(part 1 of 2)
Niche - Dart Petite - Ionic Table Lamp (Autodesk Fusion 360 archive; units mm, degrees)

design "Marble Base - Ionic Table Lamp - 120V" references "Arca Tall", "Orb 8.5In - Solitaire Petite", "T9-5In", "T8 LED 11", "T9 - Bulb", "Facet Petite", "Marble Base - Silicone Gasket", "2-Pole Plug End", "Balon v2", "Dart", "Rubber Grommet", "Neoprene Pad", "Chinois", "Dart Petite", "Marble Base - Plastic Insert", "Trove - TL"
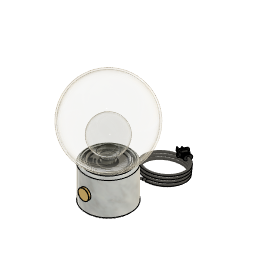
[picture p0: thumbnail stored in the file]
sketch "Sketch1" plane through (0, 0, 0) normal (0, 0, 1) x axis (1, 0, 0)
  circle C1 centre (0, 0) radius 63.5
  point P1 (0, 0)
  point P2 (0, 0)
  coincident P1 P2
extrude "Extrude1" new body sketch "Sketch1" along normal blind 101.6 bodies "Marble Base"
sketch "Sketch2" plane through (0, 0, 101.6) normal (0, 0, 1) x axis (-1, 0, 0)
  circle C1 centre (0, 0) radius 63.5
  circle C2 centre (0, 0) radius 53.975
  concentric C1 C2
  dimension "d3" diameter C2 = 107.95
extrude "Extrude2" cut sketch "Sketch2" profile of C2 against normal blind 34.925
sketch "Sketch3" plane through (0, 0, 66.675) normal (0, 0, 1) x axis (-1, 0, 0)
  circle C1 centre (0, 0) radius 53.975
  circle C2 centre (0, 0) radius 49.276
  point P1 (0, 0)
  point P3 (0, 0)
  coincident P1 P3
  dimension "d6" diameter C2 = 98.552
extrude "Extrude3" cut sketch "Sketch3" profile of C2 against normal blind 45.72
sketch "Sketch4" plane through (0, 0, 0) normal (0, 1, 0) x axis (1, 0, 0)
  circle C1 centre (0, -50.8) radius 3.81
  dimension "d9" diameter C1 = 7.62
extrude "Extrude4" cut sketch "Sketch4" against normal blind 127
sketch "Sketch5" plane through (0, 0, 0) normal (0, 1, 0) x axis (1, 0, 0)
  line L1 (0, -25.4) -> (0, 0)
  line L2 (0, -30.48) -> (0, -25.4)
  circle C1 centre (0, -30.48) radius 5.08
  point P1 (0, 0)
  point P2 (0, 0)
  point P4 (0, -30.48)
  point P5 (0, -30.48)
  coincident P1 P2
  vertical L1
  parallel L1 L2
  coincident P4 P5
  dimension "d12" diameter C1 = 10.16
extrude "Extrude5" cut sketch "Sketch5" profile of C1 along normal blind 114.3
fillet "Fillet1" radius 6.35 3.175 4.064
derived_base_feature "Derived Base Feature1" bodies "Rotary Switch"
derived_base_feature "Derived Base Feature1" bodies "Coiled - SVT (Blk Fabric)"
derived_base_feature "Derived Base Feature1" bodies "Glass Globe"
derived_base_feature "Derived Base Feature1" bodies "Metal Housing"
derived_base_feature "Derived Base Feature1" bodies "Metal Socket Cover"
derived_base_feature "Derived Base Feature1" bodies "Porcelain Socket"
derived_base_feature "Derived Base Feature1" bodies "Brass Dial - Dimmer Knob"
component_from_bodies "Body->Comp1"
offset_faces "OffsetFaces1" distance 12.7
offset_faces "OffsetFaces2" distance -12.7
derived_base_feature "Derived Base Feature1" bodies "Solitaire Petite"
move "Move1"
offset_faces "OffsetFaces1" distance 20.32
move "Move2"
extrude "Extrude6" add of existing geometry blind 25.4
offset_faces "OffsetFaces2" distance -3.81
fillet "Fillet2" radius 2.54
move "Move3"
derived_base_feature "Derived Base Feature2" bodies "Facet Petite"
move "Move4"
offset_faces "OffsetFaces1" distance 2.54
move "Move1"
derived_base_feature "Derived Base Feature1" bodies "Body1"
derived_base_feature "Derived Base Feature1" bodies "Body1"
derived_base_feature "Derived Base Feature1" bodies "Body1"
derived_base_feature "Derived Base Feature1" bodies "Body1"
derived_base_feature "Derived Base Feature1" bodies "Body1"
derived_base_feature "Derived Base Feature1" bodies "Body1", "Body2"
derived_base_feature "Derived Base Feature1" bodies "Body1"
position "Position1"
external_derived "ExternalDerived5" bodies "Plastic Insert"
derived_instance "DerivedInstance15"
offset_faces "OffsetFaces1" distance 3.81
offset_faces "OffsetFaces2" distance -1.0414
move "Move6"
external_derived "ExternalDerived6" sketch "Sketch3" bodies "Silicone Gasket"
derived_instance "DerivedInstance16"
offset_faces "OffsetFaces3" distance -10.795
move "Move1"
move_face "MoveFace1"
position "Position2"
position "Position3"
position "Position4"
position "Position5"
move "Move2"
position "Position6"
offset_faces "OffsetFaces2" distance -7.62
chamfer "Chamfer1" distance 0.381
remove_instance "RemoveInstance1"
remove_instance "RemoveInstance2"
remove_instance "RemoveInstance3"
remove_instance "RemoveInstance4"
move "Move1"
derived_base_feature "Derived Base Feature5" bodies "Oculo Petite"
align "Align1"
external_derived "ExternalDerived8"
derived_base_feature "Derived Base Feature7" bodies "Balon v2"
derived_base_feature "Derived Base Feature8" bodies "Balon v3"
align "Align3"
align "Align4"
external_derived "ExternalDerived10"
component_insert "Component Insert1"
position "Position7"
position "Position8"
derived_base_feature "Derived Base Feature11" bodies "Trove - TL"
move "Move10"
move "Move11"
remove_instance "RemoveInstance5"
split "Split1" bodies "Trove - TL (1)"
remove_body "RemoveBody2"
remove_body "RemoveBody3"
external_derived "ExternalDerived13" bodies "Trove - TL"
derived_instance "DerivedInstance20"
remove_body "RemoveBody4"
remove_body "RemoveBody5"
component_insert "Component Insert2"
component_insert "Component Insert3"
component_from_bodies "Body->Comp2"
remove_body "RemoveBody7"
move "Move12"
move "Move13"
sketch "Sketch6" plane through (0, 0, 97.917) normal (0, 0, 1) x axis (-1, 0, 0)
  circle C1 centre (0, 0) radius 41.275
  circle C2 centre (0, 0) radius 19.685
  arc A1 centre (0, 0) radius 29.3982 clockwise from (-27.6283, 10.0466) to (27.6283, 10.0466)
  arc A2 centre (0, 0) radius 26.2232 clockwise from (-24.6444, 8.9616) to (24.6444, 8.9616)
  arc A3 centre (0, 0) radius 32.5732 clockwise from (-30.6121, 11.1317) to (30.6121, 11.1317)
  arc A4 centre (0, 0) radius 35.7482 clockwise from (-33.596, 12.2167) to (33.596, 12.2167)
  point P1 (0, 0)
  point P3 (0, 0)
  coincident P1 P3
  dimension "d37" = -3.175
  dimension "d38" = 3.175
  dimension "d39" = 6.35
  dimension "d40" Text1-Height = 2.54
  dimension "d41" Text2-Height = 2.54
  dimension "d42" Text3-Height = 2.54
  dimension "d43" Text4-Height = 2.54
extrude "Extrude1" cut sketch "Sketch6" against normal blind 0.254
external_derived "ExternalDerived14" bodies "Rubber Grommet"
derived_instance "DerivedInstance19"
external_derived "ExternalDerived15" bodies "2-Pole Plug End"
derived_instance "DerivedInstance18"
external_derived "ExternalDerived16" bodies "Neoprene Pad"
derived_instance "DerivedInstance17"
position "Position9"
position "Position10"
position "Position11"
position "Position12"
external_derived "ExternalDerived17" bodies "Chinois"
derived_instance "DerivedInstance21"
position "Position13"
move "Move3"
remove_body "RemoveBody8"
component_insert "Component Insert4"
offset_faces "OffsetFaces3" distance 50.8
component_insert "Component Insert5"
position "Position14"
external_derived "ExternalDerived18" bodies "Dart Grand"
derived_instance "DerivedInstance22"
offset_faces "OffsetFaces1" distance -10.16
position "Position15"
external_derived "ExternalDerived19" bodies "Dart Petite"
derived_instance "DerivedInstance23"
offset_faces "OffsetFaces1" distance -10.16
position "Position16"
component_insert "Component Insert6"
position "Position17"
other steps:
derived_base_feature "Derived Base Feature1" bodies "Trove - TL"
derived_base_feature "Derived Base Feature1" bodies "Chinois"
derived_base_feature "Derived Base Feature1" bodies "Dart Grand"
derived_base_feature "Derived Base Feature1" bodies "Dart Petite"
derived_base_feature "Derived Base Feature1" bodies "Rubber Grommet"
derived_base_feature "Derived Base Feature1" bodies "Neoprene Pad"
derived_base_feature "Derived Base Feature1" bodies "2-Pole Plug End"
move "Move1"
derived_base_feature "Derived Base Feature1" bodies "Plastic Insert"
derived_base_feature "Derived Base Feature1" bodies "Silicone Gasket"
base_feature "Base Feature1" bodies "Oculo Petite", "Arca Petite"
base_feature "Base Feature1" bodies "Marble Base"
move "Move8"
derived_base_feature "Derived Base Feature"
create_component "CreateComponent1"
create_component "CreateComponent2"
create_component "CreateComponent3"
create_component "CreateComponent4"
create_component "CreateComponent5"
create_component "CreateComponent6"
create_component "CreateComponent7"
create_component "CreateComponent8"
remove_body "RemoveBody1"
create_component "CreateComponent9"
create_component "CreateComponent10"
create_component "CreateComponent11"
create_component "CreateComponent12"
create_component "CreateComponent13"
create_component "CreateComponent14"
create_component "CreateComponent15"
create_component "CreateComponent16"
create_component "CreateComponent17"
create_component "CreateComponent18"
remove_body "RemoveBody6"
create_component "CreateComponent19"
create_component "CreateComponent20"
create_component "CreateComponent21"
create_component "CreateComponent22"
create_component "CreateComponent23"
create_component "CreateComponent24"
create_component "CreateComponent25"
named bodies: "Marble Base", "Rotary Switch", "Coiled - SVT (Blk Fabric)", "Glass Globe", "Metal Housing", "Metal Socket Cover", "Porcelain Socket", "Brass Dial - Dimmer Knob", "Solitaire Petite", "Facet Petite", "Body1", "Body2", "Plastic Insert", "Silicone Gasket", "Oculo Petite", "Balon v2", "Balon v3", "Trove - TL", "Trove - TL (1)", "Arca Petite", "Neoprene Pad", "2-Pole Plug End", "Rubber Grommet", "Chinois", "Dart Grand", "Dart Petite"

design "Dart Petite"
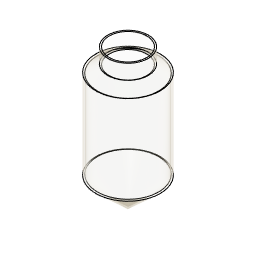
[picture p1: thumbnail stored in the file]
sketch "Sketch1" plane through (0, 0, 0) normal (0, 0, 1) x axis (1, 0, 0)
work_plane "WorkPlane1" AlongDistance 76.2
sketch "Sketch2" plane through (0, 0, 76.2) normal (0, 0, 1) x axis (1, 0, 0)
sketch "Sketch3" plane through (0, 0, 76.2) normal (0, 0, 1) x axis (1, 0, 0)
sketch "Sketch4" plane through (0, 0, 76.2) normal (0, 0, 1) x axis (1, 0, 0)
  circle C1 centre (0, 0) radius 82.55
  point P1 (0, 0)
  point P2 (0, 0)
  coincident P1 P2
  dimension "d2" diameter C1 = 165.1
loft "Loft1" sketch "Sketch4" bodies "Dart Petite"
extrude "Extrude1" add of existing geometry blind 228.6
work_plane "WorkPlane2" AlongDistance 19.05
sketch "Sketch5" plane through (0, 0, 323.85) normal (0, 0, 1) x axis (1, 0, 0)
  circle C1 centre (0, 0) radius 52.07
  point P1 (0, 0)
  point P2 (0, 0)
  coincident P1 P2
  dimension "d6" diameter C1 = 104.14
loft "Loft2" sketch "Sketch5"
extrude "Extrude2" add of existing geometry blind 38.1
shell "Shell3" innerThickness 3.81
component_from_bodies "Body->Comp"
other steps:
base_feature "Base Feature" bodies "Dart Petite"
create_component "CreateComponent1"
remove_body "RemoveBody1"
named bodies: "Dart Petite"

design "Neoprene Pad"
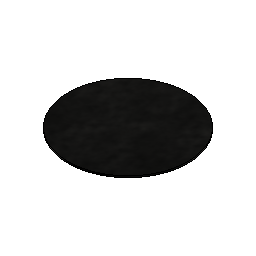
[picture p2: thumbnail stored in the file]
sketch "Sketch1" plane through (0, 0, 0) normal (0, 0, 1) x axis (1, 0, 0)
  circle C1 centre (0, 0) radius 57.15
  point P1 (0, 0)
  point P2 (0, 0)
  coincident P1 P2
extrude "Extrude1" new body sketch "Sketch1" along normal blind 1.5875 bodies "Neoprene Pad"
component_from_bodies "Body->Comp"
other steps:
base_feature "Base Feature" bodies "Neoprene Pad"
create_component "CreateComponent1"
remove_body "RemoveBody1"
named bodies: "Neoprene Pad"

design "T9 - Bulb"
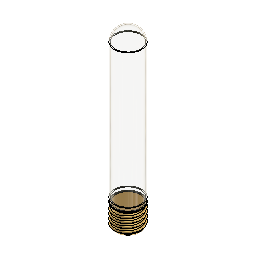
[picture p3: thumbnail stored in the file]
sketch "Sketch1" plane through (0, 0, 0) normal (0, 1, 0) x axis (1, 0, 0)
  line L1 (0, -166.37) -> (0, 0)
  line L2 (13.97, -13.97) -> (13.97, -152.4)
  line L3 (-13.97, -152.4) -> (-13.97, -13.97)
  line L4 (0, 0) -> (0, -166.37)
  line L5 (12.97, -13.97) -> (12.97, -152.4)
  line L6 (-12.97, -152.4) -> (-12.97, -13.97)
  line L7 (-12.3978, -10.16) -> (-13.4404, -10.16)
  line L8 (13.4404, -10.16) -> (12.3978, -10.16)
  arc A1 centre (0, -152.4) radius 13.97 clockwise from (13.97, -152.4) to (-13.97, -152.4)
  arc A2 centre (0, -152.4) radius 12.97 clockwise from (12.97, -152.4) to (-12.97, -152.4)
  arc A3 centre (0, -13.97) radius 13.97 clockwise from (13.4404, -10.16) to (13.97, -13.97)
  arc A4 centre (0, -13.97) radius 13.97 clockwise from (-13.97, -13.97) to (-13.4404, -10.16)
  arc A5 centre (0, -13.97) radius 12.97 clockwise from (12.3978, -10.16) to (12.97, -13.97)
  arc A6 centre (0, -13.97) radius 12.97 clockwise from (-12.97, -13.97) to (-12.3978, -10.16)
  point P1 (0, 0)
  point P2 (0, 0)
  point P3 (0, -166.37)
  point P10 (0, 0)
  point P17 (13.4404, -10.16)
  point P19 (12.3978, -10.16)
  point P4 (13.97, -152.4)
  point P5 (13.97, -13.97)
  coincident P1 P2
  vertical L1
  tangent L2 A3
  tangent L3 A3
  parallel L2 L3
  tangent L3 A1
  tangent L2 A1
  midpoint P3 A1
  coincident P1 P10
  perpendicular L1 L7
  coincident P17 L7
  concentric A3 A4
  coincident P10 A3
  concentric A1 A2
  tangent L5 A2
  tangent L5 A5
  tangent L6 A5
  tangent L6 A2
  coincident P19 L7
  concentric A5 A6
  collinear L7 L8
  dimension "d6" distance L2 L3 = 27.94
  dimension "d7" distance P4 P5 = 138.43
revolve "Revolve1" sketch "Sketch1" AlongAngle 360 bodies "T9"
derived_base_feature "Derived Base Feature" bodies "E26 Base"
align "Align1"
move "Move1"
component_from_bodies "Body->Comp1"
component_from_bodies "Body->Comp2"
copy_paste "CutPaste1"
copy_paste "CutPaste2"
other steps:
base_feature "Base Feature1" bodies "T9"
base_feature "Base Feature1" bodies "E26 Base"
create_component "CreateComponent1"
create_component "CreateComponent2"
remove_body "RemoveBody1"
create_component "CreateComponent3"
remove_body "RemoveBody2"
remove_instance "RemoveInstance1"
remove_instance "RemoveInstance2"
named bodies: "T9", "E26 Base"

design "Facet Petite"
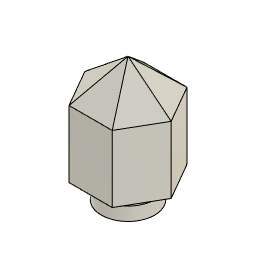
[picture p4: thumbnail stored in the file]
sketch "Sketch7" plane through (0, 0, 0) normal (1, 0, 0) x axis (0, 1, 0)
sketch "Sketch8" plane through (0, 0, 0) normal (0, 0, 1) x axis (1, 0, 0)
  circle C1 centre (0, 0) radius 50.8
  point P1 (0, 0)
  point P2 (0, 0)
  coincident P1 P2
  dimension "d17" diameter C1 = 101.6
extrude "Extrude5" new body sketch "Sketch8" along normal blind 25.4 and against normal blind 25.4
work_plane "WorkPlane1" AlongDistance 17.78
sketch "Sketch10" plane through (0, 0, 25.4) normal (0, 0, 1) x axis (-1, 0, 0)
  circle C1 centre (0, 0) radius 50.8
sketch "Sketch12" plane through (0, 0, 43.18) normal (0, 0, 1) x axis (1, 0, 0)
  line L1 (-82.1223, 0) -> (-41.0612, 71.12)
  line L2 (-41.0612, -71.12) -> (-82.1223, 0)
  line L3 (41.0612, -71.12) -> (-41.0612, -71.12)
  line L4 (82.1223, 0) -> (41.0612, -71.12)
  line L5 (41.0612, 71.12) -> (82.1223, 0)
  line L6 (-41.0612, 71.12) -> (41.0612, 71.12)
  point P1 (0, 0)
  point P8 (0, 0)
  coincident P1 P8
  dimension "d22" distance P8 L6 = 71.12
sketch "Sketch15" plane through (0, 0, 0) normal (0, 1, 0) x axis (1, 0, 0)
  line L1 (53.7365, -21.6801) -> (82.1223, -43.18)
  line L2 (-50.8, -25.4) -> (-82.1223, -43.18)
  point P2 (82.1223, -43.18)
  point P3 (82.1223, -43.18)
  point P5 (-82.1223, -43.18)
  point P7 (-82.1223, -43.18)
  point P6 (-50.8, -25.4)
  point P8 (-50.8, -25.4)
  coincident P2 P3
  coincident P5 P7
  coincident P6 P8
sketch "Sketch17" plane through (0, 0, 25.4) normal (0, 0, 1) x axis (-1, 0, 0)
  line L1 (51.3255, 0) -> (0, 0)
  line L2 (73.3235, 0) -> (0, 0)
  line L3 (-41.0612, -71.12) -> (-25.4, -43.9941)
  line L4 (-36.6617, -63.5) -> (-25.4, -43.9941)
  line L5 (78.4305, 0) -> (0, 0)
  line L6 (41.0612, -71.12) -> (25.4, -43.9941)
  line L7 (25.4, 43.9941) -> (41.0612, 71.12)
  line L8 (73.3235, 0) -> (0, 0)
  line L9 (-25.4, 43.9941) -> (-41.0612, 71.12)
  line L10 (0, 0) -> (0, 0)
  circle C1 centre (0, 0) radius 50.8
  point P1 (0, 0)
  point P4 (0, 0)
  point P2 (-41.0612, -71.12)
  point P6 (-41.0612, -71.12)
  point P3 (0, 0)
  point P7 (0, 0)
  point P9 (-25.4, -43.9941)
  point P12 (41.0612, -71.12)
  point P13 (41.0612, -71.12)
  point P15 (25.4, -43.9941)
  point P16 (41.0612, 71.12)
  point P17 (41.0612, 71.12)
  point P18 (25.4, 43.9941)
  point P19 (-41.0612, 71.12)
  point P20 (-41.0612, 71.12)
  point P21 (0, 0)
  point P23 (-25.4, 43.9941)
  point P25 (0, 0)
  point P24 (0, 0)
  point P26 (0, 0)
  horizontal L1
  coincident P1 P4
  coincident P2 P6
  horizontal L2
  coincident P3 P7
  coincident C1 P9
  coincident P12 P13
  horizontal L5
  coincident C1 P15
  coincident P16 P17
  coincident C1 P18
  coincident P19 P20
  horizontal L8
  coincident P1 P21
  coincident C1 P23
  coincident P1 P25
  coincident P24 P26
extrude "Extrude6" new body sketch "Sketch12" along normal blind 127
work_plane "WorkPlane2" AlongDistance 66.04
sketch "Sketch18" plane through (0, 0, 236.22) normal (0, 0, 1) x axis (1, 0, 0)
  line L1 (41.0612, -71.12) -> (0, 0)
  line L2 (82.1223, 0) -> (0, 0)
  line L3 (41.0612, 71.12) -> (0, 0)
  line L4 (-41.0612, 71.12) -> (0, 0)
  line L5 (-82.1223, 0) -> (0, 0)
  line L6 (-41.0612, -71.12) -> (0, 0)
  point P1 (0, 0)
  point P3 (0, 0)
  point P2 (41.0612, -71.12)
  point P4 (41.0612, -71.12)
  point P6 (0, 0)
  point P5 (82.1223, 0)
  point P7 (82.1223, 0)
  point P9 (0, 0)
  point P8 (41.0612, 71.12)
  point P10 (41.0612, 71.12)
  point P12 (0, 0)
  point P11 (-41.0612, 71.12)
  point P13 (-41.0612, 71.12)
  point P15 (0, 0)
  point P14 (-82.1223, 0)
  point P16 (-82.1223, 0)
  point P18 (0, 0)
  point P17 (-41.0612, -71.12)
  point P19 (-41.0612, -71.12)
  coincident P1 P3
  coincident P2 P4
  coincident P1 P6
  coincident P5 P7
  coincident P1 P9
  coincident P8 P10
  coincident P1 P12
  coincident P11 P13
  coincident P1 P15
  coincident P14 P16
  coincident P1 P18
  coincident P17 P19
loft "Loft1"
loft "Loft2" sketch "Sketch17"
component_from_bodies "Body->Comp"
extrude "Extrude1" cut of existing geometry blind -25.4
shell "Shell2" innerThickness 3.81
fillet "Fillet1" radius 7.62
fillet "Fillet2" radius 6.35
fillet "Fillet3" radius 6.35
fillet "Fillet4" radius 6.35
fillet "Fillet5" radius 6.35
fillet "Fillet6" radius 6.35
fillet "Fillet7" radius 3.81
fillet "Fillet8" radius 6.35
fillet "Fillet9" radius 6.35
fillet "Fillet10" radius 6.35
fillet "Fillet11" radius 6.35
fillet "Fillet12" radius 6.35
fillet "Fillet13" radius 2.286
shell "Shell1" innerThickness 2.54
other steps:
base_feature "Base Feature"
create_component "CreateComponent3"
remove_body "RemoveBody2"

design "Marble Base - Silicone Gasket"
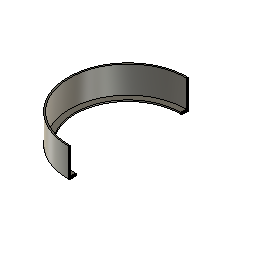
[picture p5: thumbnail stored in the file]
sketch "Sketch1" plane through (0, 0, 0) normal (0, 0, 1) x axis (1, 0, 0)
  circle C1 centre (0, 0) radius 53.34
  point P1 (0, 0)
  point P2 (0, 0)
  coincident P1 P2
extrude "Extrude1" new body sketch "Sketch1" along normal blind 25.4 bodies "Silicone Gasket"
shell "Shell1" innerThickness 1.27
sketch "Sketch2" plane through (0, 0, 1.27) normal (0, 0, 1) x axis (-1, 0, 0)
  circle C1 centre (0, 0) radius 52.07
  circle C2 centre (0, 0) radius 46.99
  concentric C1 C2
extrude "Extrude2" cut sketch "Sketch2" profile of C2 against normal blind 12.7
component_from_bodies "Body->Comp"
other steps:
base_feature "Base Feature" bodies "Silicone Gasket"
create_component "CreateComponent1"
remove_body "RemoveBody1"
named bodies: "Silicone Gasket"

design "Balon v2"
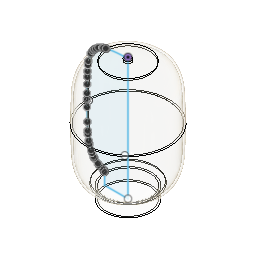
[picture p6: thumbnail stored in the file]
derived_base_feature "Derived Base Feature" bodies "Balon"
work_plane "WorkPlane1" AlongDistance 0
sketch "Sketch1" plane through (0, 0, 0) normal (0, 1, 0) x axis (1, 0, 0)
  line L1 (0, 317.5) -> (0, 2.9083)
  curve K1 (-82.9821, 124.2212) -> (-50.8, 237.8015)
  curve K2 (-51.0925, 237.681) -> (-50.8, 237.8015)
  curve K3 (-51.3855, 237.5558) -> (-51.0925, 237.681)
  curve K4 (-54.7608, 236.0513) -> (-51.3855, 237.5558)
  curve K5 (-57.9615, 234.05) -> (-54.7608, 236.0513)
  curve K6 (-67.2727, 226.749) -> (-57.9615, 234.05)
  curve K7 (-69.0552, 224.2615) -> (-67.2727, 226.749)
  curve K8 (-72.1872, 218.7832) -> (-69.0552, 224.2615)
  curve K9 (-74.1213, 215.1556) -> (-72.1872, 218.7832)
  curve K10 (-78.3031, 204.3965) -> (-74.1213, 215.1556)
  curve K11 (-79.7275, 197.3397) -> (-78.3031, 204.3965)
  curve K12 (-81.3333, 185.4664) -> (-79.7275, 197.3397)
  curve K13 (-81.6254, 178.4008) -> (-81.3333, 185.4664)
  curve K14 (-82.49, 152.2133) -> (-81.6254, 178.4008)
  curve K15 (-82.9821, 136.067) -> (-82.49, 152.2133)
  curve K16 (-82.9821, 124.2212) -> (-82.9821, 136.067)
  curve K17 (50.8, 237.7999) -> (82.9821, 124.2212)
  curve K18 (82.9821, 140.3031) -> (82.9821, 124.2212)
  curve K19 (81.9353, 169.4257) -> (82.9821, 140.3031)
  curve K20 (81.3621, 183.6489) -> (81.9353, 169.4257)
  curve K21 (80.9478, 189.8724) -> (81.3621, 183.6489)
  curve K22 (77.8147, 206.9858) -> (80.9478, 189.8724)
  curve K23 (74.9652, 213.2153) -> (77.8147, 206.9858)
  curve K24 (69.4688, 224.1531) -> (74.9652, 213.2153)
  curve K25 (67.2512, 226.458) -> (69.4688, 224.1531)
  curve K26 (61.5696, 231.3138) -> (67.2512, 226.458)
  curve K27 (57.377, 234.6711) -> (61.5696, 231.3138)
  curve K28 (52.0556, 237.2628) -> (57.377, 234.6711)
  curve K29 (51.4313, 237.5413) -> (52.0556, 237.2628)
  curve K30 (50.8, 237.7999) -> (51.4313, 237.5413)
  line L2 (-50.8, 317.5) -> (-50.8, 237.8015)
  line L3 (50.8, 317.5) -> (50.8, 237.7999)
  line L4 (-19.0713, 6.7501) -> (-19.0713, 6.7501)
  curve K31 (82.9821, 124.1958) -> (40.1509, 7.3012)
  curve K32 (41.8198, 7.6176) -> (40.1509, 7.3012)
  curve K33 (43.2113, 8.0663) -> (41.8198, 7.6176)
  curve K34 (47.0139, 9.2854) -> (43.2113, 8.0663)
  curve K35 (47.3314, 9.3805) -> (47.0139, 9.2854)
  curve K36 (50.1192, 10.3272) -> (47.3314, 9.3805)
  curve K37 (51.833, 11.0085) -> (50.1192, 10.3272)
  curve K38 (57.8313, 14.1895) -> (51.833, 11.0085)
  curve K39 (61.4491, 17.0488) -> (57.8313, 14.1895)
  curve K40 (66.8203, 21.5867) -> (61.4491, 17.0488)
  curve K41 (68.5372, 23.5528) -> (66.8203, 21.5867)
  curve K42 (71.2201, 27.8971) -> (68.5372, 23.5528)
  curve K43 (74.7424, 33.8984) -> (71.2201, 27.8971)
  curve K44 (78.2342, 44.8406) -> (74.7424, 33.8984)
  curve K45 (79.6792, 50.3463) -> (78.2342, 44.8406)
  curve K46 (81.3558, 63.5576) -> (79.6792, 50.3463)
  curve K47 (81.6386, 70.4415) -> (81.3558, 63.5576)
  curve K48 (82.4897, 96.2198) -> (81.6386, 70.4415)
  curve K49 (82.9814, 112.3523) -> (82.4897, 96.2198)
  curve K50 (82.9821, 124.1958) -> (82.9814, 112.3523)
  curve K51 (-40.1501, 7.301) -> (-82.9821, 124.1958)
  curve K52 (-82.9813, 110.5256) -> (-82.9821, 124.1958)
  curve K53 (-82.2545, 88.8594) -> (-82.9813, 110.5256)
  curve K54 (-81.6277, 70.519) -> (-82.2545, 88.8594)
  curve K55 (-81.3572, 64.3441) -> (-81.6277, 70.519)
  curve K56 (-79.4149, 46.8924) -> (-81.3572, 64.3441)
  curve K57 (-76.5204, 38.9768) -> (-79.4149, 46.8924)
  curve K58 (-73.5142, 32.2947) -> (-76.5204, 38.9768)
  curve K59 (-72.5556, 30.3818) -> (-73.5142, 32.2947)
  curve K60 (-69.7914, 25.3691) -> (-72.5556, 30.3818)
  curve K61 (-68.3824, 23.4028) -> (-69.7914, 25.3691)
  curve K62 (-64.5419, 19.5456) -> (-68.3824, 23.4028)
  curve K63 (-62.3002, 17.7646) -> (-64.5419, 19.5456)
  curve K64 (-53.6583, 11.1976) -> (-62.3002, 17.7646)
  curve K65 (-49.6968, 10.1396) -> (-53.6583, 11.1976)
  curve K66 (-43.4141, 8.1331) -> (-49.6968, 10.1396)
  curve K67 (-41.9704, 7.6516) -> (-43.4141, 8.1331)
  curve K68 (-40.1963, 7.3098) -> (-41.9704, 7.6516)
  curve K69 (-40.1732, 7.3054) -> (-40.1963, 7.3098)
  curve K70 (-40.1501, 7.301) -> (-40.1732, 7.3054)
  line L5 (-82.9821, 124.1958) -> (-82.9821, 124.2212)
  line L6 (82.9821, 124.2212) -> (82.9821, 124.1958)
  line L7 (0, 317.5) -> (-50.8, 317.5)
  line L8 (7.2015, 3.048) -> (0, 3.048)
  line L9 (0, 3.048) -> (-7.2015, 3.048)
  arc A1 centre (0, 188.595) radius 185.6867 clockwise from (-7.2015, 3.048) to (-40.1502, 7.301)
  arc A2 centre (0, 188.595) radius 185.6867 clockwise from (40.151, 7.3012) to (7.2015, 3.048)
  point P38 (-40.1502, 7.301)
  point P43 (40.1509, 7.3012)
  point P62 (-40.1501, 7.301)
  point P81 (40.151, 7.3012)
  point P84 (0, 3.048)
  vertical L1
  horizontal L4
  coincident P38 K51
  symmetric L1 A1 A2
  coincident A2 P43
  coincident A1 P62
  coincident K31 P81
  perpendicular L2 L7
  horizontal L8
  coincident L1 P84
  horizontal L9
revolve "Revolve1" sketch "Sketch1" AlongAngle 360
shell "Shell1" innerThickness 3.81
fillet "Fillet1" radius 6.35
offset_faces "OffsetFaces1" distance -50.8
move "Move1"
move "Move2"
component_from_bodies "Body->Comp1"
component_from_bodies "Body->Comp2"
sketch "Sketch2" plane through (0, 0, 0) normal (0, 1, 0) x axis (1, 0, 0)
  line L1 (-85.5221, 124.2212) -> (-85.5221, 124.1961)
  curve K1 (-58.9057, 236.4383) -> (-50.8, 241.7989)
  curve K2 (-50.8, 241.554) -> (-50.8, 241.7989)
  curve K3 (-50.904, 240.933) -> (-50.8, 241.554)
  curve K4 (-51.2936, 240.2837) -> (-50.904, 240.933)
  curve K5 (-51.734, 239.7561) -> (-51.2936, 240.2837)
  curve K6 (-53.328, 238.5038) -> (-51.734, 239.7561)
  curve K7 (-54.0892, 238.1997) -> (-53.328, 238.5038)
  curve K8 (-58.9057, 236.4383) -> (-54.0892, 238.1997)
  curve K9 (-89.3309, 124.2212) -> (-58.9057, 236.4383)
  curve K10 (-62.6336, 234.9735) -> (-58.9057, 236.4383)
  curve K11 (-65.581, 233.1032) -> (-62.6336, 234.9735)
  curve K12 (-73.0224, 227.0019) -> (-65.581, 233.1032)
  curve K13 (-74.8981, 224.836) -> (-73.0224, 227.0019)
  curve K14 (-78.1104, 219.6097) -> (-74.8981, 224.836)
  curve K15 (-80.2663, 215.561) -> (-78.1104, 219.6097)
  curve K16 (-84.0943, 205.8277) -> (-80.2663, 215.561)
  curve K17 (-85.4655, 200.1154) -> (-84.0943, 205.8277)
  curve K18 (-87.4092, 188.5789) -> (-85.4655, 200.1154)
  curve K19 (-87.7349, 182.3889) -> (-87.4092, 188.5789)
  curve K20 (-88.4233, 165.9645) -> (-87.7349, 182.3889)
  curve K21 (-89.328, 138.6964) -> (-88.4233, 165.9645)
  curve K22 (-89.3309, 124.2212) -> (-89.328, 138.6964)
  line L2 (-89.3309, 124.1958) -> (-89.3309, 124.2212)
  curve K23 (-46.5001, 7.301) -> (-89.3309, 124.1958)
  curve K24 (-89.3314, 112.4293) -> (-89.3309, 124.1958)
  curve K25 (-88.8181, 95.3068) -> (-89.3314, 112.4293)
  curve K26 (-88.346, 81.2892) -> (-88.8181, 95.3068)
  curve K27 (-88.0298, 70.4902) -> (-88.346, 81.2892)
  curve K28 (-87.1514, 58.328) -> (-88.0298, 70.4902)
  curve K29 (-86.3326, 50.6119) -> (-87.1514, 58.328)
  curve K30 (-81.0932, 33.6688) -> (-86.3326, 50.6119)
  curve K31 (-77.3163, 27.4309) -> (-81.0932, 33.6688)
  curve K32 (-74.8955, 23.6666) -> (-77.3163, 27.4309)
  curve K33 (-73.5108, 22.0741) -> (-74.8955, 23.6666)
  curve K34 (-70.2346, 19.0457) -> (-73.5108, 22.0741)
  curve K35 (-64.8094, 14.3548) -> (-70.2346, 19.0457)
  curve K36 (-56.6696, 10.3041) -> (-64.8094, 14.3548)
  curve K37 (-54.0053, 9.483) -> (-56.6696, 10.3041)
  curve K38 (-49.1487, 7.9411) -> (-54.0053, 9.483)
  curve K39 (-48.3482, 7.6526) -> (-49.1487, 7.9411)
  curve K40 (-46.5001, 7.301) -> (-48.3482, 7.6526)
  line L3 (0, 266.7) -> (0, 0)
  line L4 (0, 3.048) -> (-7.7894, 3.048)
  line L5 (-50.8, 266.7) -> (-50.8, 241.7989)
  line L6 (0, 266.7) -> (-50.8, 266.7)
  arc A1 centre (-6.9779, 188.7329) radius 185.6867 clockwise from (-7.7894, 3.048) to (-46.5001, 7.301)
  point P1 (0, 0)
  point P44 (0, 0)
  point P46 (0, 3.048)
  point P5 (-50.8, 241.554)
  point P49 (0, 266.7)
  coincident P1 P44
  coincident L3 P46
  coincident P5 L5
  coincident L3 P49
revolve "Revolve2" sketch "Sketch2" AlongAngle 360 bodies "Balon v3"
shell "Shell2" innerThickness 3.81
component_from_bodies "Body->Comp3"
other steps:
base_feature "Base Feature1" bodies "Balon"
base_feature "Base Feature1" bodies "Balon v3"
base_feature "Base Feature1" bodies "Balon v2"
create_component "CreateComponent1"
remove_body "RemoveBody1"
create_component "CreateComponent2"
remove_body "RemoveBody2"
create_component "CreateComponent3"
remove_body "RemoveBody3"
named bodies: "Balon", "Balon v2", "Balon v3"

design "Arca Tall"
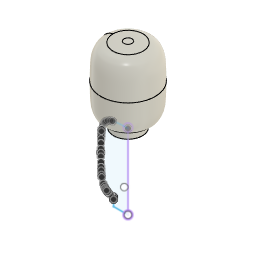
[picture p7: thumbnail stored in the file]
derived_base_feature "Derived Base Feature" bodies "Balon"
work_plane "WorkPlane1" AlongDistance 0
sketch "Sketch1" plane through (0, 0, 0) normal (0, 1, 0) x axis (1, 0, 0)
  line L1 (0, 317.5) -> (0, 2.9083)
  curve K1 (-82.9821, 124.2212) -> (-50.8, 237.8015)
  curve K2 (-51.0925, 237.681) -> (-50.8, 237.8015)
  curve K3 (-51.3855, 237.5558) -> (-51.0925, 237.681)
  curve K4 (-54.7608, 236.0513) -> (-51.3855, 237.5558)
  curve K5 (-57.9615, 234.05) -> (-54.7608, 236.0513)
  curve K6 (-67.2727, 226.749) -> (-57.9615, 234.05)
  curve K7 (-69.0552, 224.2615) -> (-67.2727, 226.749)
  curve K8 (-72.1872, 218.7832) -> (-69.0552, 224.2615)
  curve K9 (-74.1213, 215.1556) -> (-72.1872, 218.7832)
  curve K10 (-78.3031, 204.3965) -> (-74.1213, 215.1556)
  curve K11 (-79.7275, 197.3397) -> (-78.3031, 204.3965)
  curve K12 (-81.3333, 185.4664) -> (-79.7275, 197.3397)
  curve K13 (-81.6254, 178.4008) -> (-81.3333, 185.4664)
  curve K14 (-82.49, 152.2133) -> (-81.6254, 178.4008)
  curve K15 (-82.9821, 136.067) -> (-82.49, 152.2133)
  curve K16 (-82.9821, 124.2212) -> (-82.9821, 136.067)
  curve K17 (50.8, 237.7999) -> (82.9821, 124.2212)
  curve K18 (82.9821, 140.3031) -> (82.9821, 124.2212)
  curve K19 (81.9353, 169.4257) -> (82.9821, 140.3031)
  curve K20 (81.3621, 183.6489) -> (81.9353, 169.4257)
  curve K21 (80.9478, 189.8724) -> (81.3621, 183.6489)
  curve K22 (77.8147, 206.9858) -> (80.9478, 189.8724)
  curve K23 (74.9652, 213.2153) -> (77.8147, 206.9858)
  curve K24 (69.4688, 224.1531) -> (74.9652, 213.2153)
  curve K25 (67.2512, 226.458) -> (69.4688, 224.1531)
  curve K26 (61.5696, 231.3138) -> (67.2512, 226.458)
  curve K27 (57.377, 234.6711) -> (61.5696, 231.3138)
  curve K28 (52.0556, 237.2628) -> (57.377, 234.6711)
  curve K29 (51.4313, 237.5413) -> (52.0556, 237.2628)
  curve K30 (50.8, 237.7999) -> (51.4313, 237.5413)
  line L2 (-50.8, 317.5) -> (-50.8, 237.8015)
  line L3 (50.8, 317.5) -> (50.8, 237.7999)
  line L4 (-19.0713, 6.7501) -> (-19.0713, 6.7501)
  curve K31 (82.9821, 124.1958) -> (40.1509, 7.3012)
  curve K32 (41.8198, 7.6176) -> (40.1509, 7.3012)
  curve K33 (43.2113, 8.0663) -> (41.8198, 7.6176)
  curve K34 (47.0139, 9.2854) -> (43.2113, 8.0663)
  curve K35 (47.3314, 9.3805) -> (47.0139, 9.2854)
  curve K36 (50.1192, 10.3272) -> (47.3314, 9.3805)
  curve K37 (51.833, 11.0085) -> (50.1192, 10.3272)
  curve K38 (57.8313, 14.1895) -> (51.833, 11.0085)
  curve K39 (61.4491, 17.0488) -> (57.8313, 14.1895)
  curve K40 (66.8203, 21.5867) -> (61.4491, 17.0488)
  curve K41 (68.5372, 23.5528) -> (66.8203, 21.5867)
  curve K42 (71.2201, 27.8971) -> (68.5372, 23.5528)
  curve K43 (74.7424, 33.8984) -> (71.2201, 27.8971)
  curve K44 (78.2342, 44.8406) -> (74.7424, 33.8984)
  curve K45 (79.6792, 50.3463) -> (78.2342, 44.8406)
  curve K46 (81.3558, 63.5576) -> (79.6792, 50.3463)
  curve K47 (81.6386, 70.4415) -> (81.3558, 63.5576)
  curve K48 (82.4897, 96.2198) -> (81.6386, 70.4415)
  curve K49 (82.9814, 112.3523) -> (82.4897, 96.2198)
  curve K50 (82.9821, 124.1958) -> (82.9814, 112.3523)
  curve K51 (-40.1501, 7.301) -> (-82.9821, 124.1958)
  curve K52 (-82.9813, 110.5256) -> (-82.9821, 124.1958)
  curve K53 (-82.2545, 88.8594) -> (-82.9813, 110.5256)
  curve K54 (-81.6277, 70.519) -> (-82.2545, 88.8594)
  curve K55 (-81.3572, 64.3441) -> (-81.6277, 70.519)
  curve K56 (-79.4149, 46.8924) -> (-81.3572, 64.3441)
  curve K57 (-76.5204, 38.9768) -> (-79.4149, 46.8924)
  curve K58 (-73.5142, 32.2947) -> (-76.5204, 38.9768)
  curve K59 (-72.5556, 30.3818) -> (-73.5142, 32.2947)
  curve K60 (-69.7914, 25.3691) -> (-72.5556, 30.3818)
  curve K61 (-68.3824, 23.4028) -> (-69.7914, 25.3691)
  curve K62 (-64.5419, 19.5456) -> (-68.3824, 23.4028)
  curve K63 (-62.3002, 17.7646) -> (-64.5419, 19.5456)
  curve K64 (-53.6583, 11.1976) -> (-62.3002, 17.7646)
  curve K65 (-49.6968, 10.1396) -> (-53.6583, 11.1976)
  curve K66 (-43.4141, 8.1331) -> (-49.6968, 10.1396)
  curve K67 (-41.9704, 7.6516) -> (-43.4141, 8.1331)
  curve K68 (-40.1963, 7.3098) -> (-41.9704, 7.6516)
  curve K69 (-40.1732, 7.3054) -> (-40.1963, 7.3098)
  curve K70 (-40.1501, 7.301) -> (-40.1732, 7.3054)
  line L5 (-82.9821, 124.1958) -> (-82.9821, 124.2212)
  line L6 (82.9821, 124.2212) -> (82.9821, 124.1958)
  line L7 (0, 317.5) -> (-50.8, 317.5)
  line L8 (7.2015, 3.048) -> (0, 3.048)
  line L9 (0, 3.048) -> (-7.2015, 3.048)
  arc A1 centre (0, 188.595) radius 185.6867 clockwise from (-7.2015, 3.048) to (-40.1502, 7.301)
  arc A2 centre (0, 188.595) radius 185.6867 clockwise from (40.151, 7.3012) to (7.2015, 3.048)
  point P38 (-40.1502, 7.301)
  point P43 (40.1509, 7.3012)
  point P62 (-40.1501, 7.301)
  point P81 (40.151, 7.3012)
  point P84 (0, 3.048)
  vertical L1
  horizontal L4
  coincident P38 K51
  symmetric L1 A1 A2
  coincident A2 P43
  coincident A1 P62
  coincident K31 P81
  perpendicular L2 L7
  horizontal L8
  coincident L1 P84
  horizontal L9
revolve "Revolve1" sketch "Sketch1" AlongAngle 360
shell "Shell1" innerThickness 3.81
fillet "Fillet1" radius 6.35 bodies "Balon v3"
offset_faces "OffsetFaces1" distance -50.8
move "Move1"
move "Move2"
component_from_bodies "Body->Comp1"
component_from_bodies "Body->Comp2"
sketch "Sketch2" plane through (0, 0, 0) normal (0, 1, 0) x axis (1, 0, 0)
  line L1 (-85.5221, 124.2212) -> (-85.5221, 124.1961)
  curve K1 (-58.9057, 236.4383) -> (-50.8, 241.7989)
  curve K2 (-50.8, 241.554) -> (-50.8, 241.7989)
  curve K3 (-50.904, 240.933) -> (-50.8, 241.554)
  curve K4 (-51.2936, 240.2837) -> (-50.904, 240.933)
  curve K5 (-51.734, 239.7561) -> (-51.2936, 240.2837)
  curve K6 (-53.328, 238.5038) -> (-51.734, 239.7561)
  curve K7 (-54.0892, 238.1997) -> (-53.328, 238.5038)
  curve K8 (-58.9057, 236.4383) -> (-54.0892, 238.1997)
  curve K9 (-89.3309, 124.2212) -> (-58.9057, 236.4383)
  curve K10 (-62.6336, 234.9735) -> (-58.9057, 236.4383)
  curve K11 (-65.581, 233.1032) -> (-62.6336, 234.9735)
  curve K12 (-73.0224, 227.0019) -> (-65.581, 233.1032)
  curve K13 (-74.8981, 224.836) -> (-73.0224, 227.0019)
  curve K14 (-78.1104, 219.6097) -> (-74.8981, 224.836)
  curve K15 (-80.2663, 215.561) -> (-78.1104, 219.6097)
  curve K16 (-84.0943, 205.8277) -> (-80.2663, 215.561)
  curve K17 (-85.4655, 200.1154) -> (-84.0943, 205.8277)
  curve K18 (-87.4092, 188.5789) -> (-85.4655, 200.1154)
  curve K19 (-87.7349, 182.3889) -> (-87.4092, 188.5789)
  curve K20 (-88.4233, 165.9645) -> (-87.7349, 182.3889)
  curve K21 (-89.328, 138.6964) -> (-88.4233, 165.9645)
  curve K22 (-89.3309, 124.2212) -> (-89.328, 138.6964)
  line L2 (-89.3309, 124.1958) -> (-89.3309, 124.2212)
  curve K23 (-46.5001, 7.301) -> (-89.3309, 124.1958)
  curve K24 (-89.3314, 112.4293) -> (-89.3309, 124.1958)
  curve K25 (-88.8181, 95.3068) -> (-89.3314, 112.4293)
  curve K26 (-88.346, 81.2892) -> (-88.8181, 95.3068)
  curve K27 (-88.0298, 70.4902) -> (-88.346, 81.2892)
  curve K28 (-87.1514, 58.328) -> (-88.0298, 70.4902)
  curve K29 (-86.3326, 50.6119) -> (-87.1514, 58.328)
  curve K30 (-81.0932, 33.6688) -> (-86.3326, 50.6119)
  curve K31 (-77.3163, 27.4309) -> (-81.0932, 33.6688)
  curve K32 (-74.8955, 23.6666) -> (-77.3163, 27.4309)
  curve K33 (-73.5108, 22.0741) -> (-74.8955, 23.6666)
  curve K34 (-70.2346, 19.0457) -> (-73.5108, 22.0741)
  curve K35 (-64.8094, 14.3548) -> (-70.2346, 19.0457)
  curve K36 (-56.6696, 10.3041) -> (-64.8094, 14.3548)
  curve K37 (-54.0053, 9.483) -> (-56.6696, 10.3041)
  curve K38 (-49.1487, 7.9411) -> (-54.0053, 9.483)
  curve K39 (-48.3482, 7.6526) -> (-49.1487, 7.9411)
  curve K40 (-46.5001, 7.301) -> (-48.3482, 7.6526)
  line L3 (0, 266.7) -> (0, 0)
  line L4 (0, 3.048) -> (-7.7894, 3.048)
  line L5 (-50.8, 266.7) -> (-50.8, 241.7989)
  line L6 (0, 266.7) -> (-50.8, 266.7)
  arc A1 centre (-6.9779, 188.7329) radius 185.6867 clockwise from (-7.7894, 3.048) to (-46.5001, 7.301)
  point P1 (0, 0)
  point P44 (0, 0)
  point P46 (0, 3.048)
  point P5 (-50.8, 241.554)
  point P49 (0, 266.7)
  coincident P1 P44
  coincident L3 P46
  coincident P5 L5
  coincident L3 P49
revolve "Revolve2" sketch "Sketch2" AlongAngle 360 bodies "Balon v3"
shell "Shell2" innerThickness 3.81
component_from_bodies "Body->Comp3"
remove_instance "RemoveInstance1"
remove_instance "RemoveInstance2"
sketch "Sketch1" plane through (0, 0, 0) normal (0, 1, 0) x axis (1, 0, 0)
  line L1 (-6.35, 3.048) -> (-14.1394, 3.048)
  curve K1 (-52.8501, 7.301) -> (-95.6809, 124.1958)
  curve K2 (-95.6814, 112.4293) -> (-95.6809, 124.1958)
  curve K3 (-95.1681, 95.3068) -> (-95.6814, 112.4293)
  curve K4 (-94.696, 81.2892) -> (-95.1681, 95.3068)
  curve K5 (-94.3798, 70.4902) -> (-94.696, 81.2892)
  curve K6 (-93.5014, 58.328) -> (-94.3798, 70.4902)
  curve K7 (-92.6826, 50.6119) -> (-93.5014, 58.328)
  curve K8 (-87.4432, 33.6688) -> (-92.6826, 50.6119)
  curve K9 (-83.6663, 27.4309) -> (-87.4432, 33.6688)
  curve K10 (-81.2455, 23.6666) -> (-83.6663, 27.4309)
  curve K11 (-79.8608, 22.0741) -> (-81.2455, 23.6666)
  curve K12 (-76.5846, 19.0457) -> (-79.8608, 22.0741)
  curve K13 (-71.12, 13.97) -> (-76.5846, 19.0457)
  curve K14 (-62.23, 10.16) -> (-71.12, 13.97)
  curve K15 (-60.3553, 9.483) -> (-62.23, 10.16)
  curve K16 (-55.4987, 7.9411) -> (-60.3553, 9.483)
  curve K17 (-54.6982, 7.6526) -> (-55.4987, 7.9411)
  curve K18 (-52.8501, 7.301) -> (-54.6982, 7.6526)
  line L2 (-95.6809, 124.1958) -> (-95.6809, 124.2212)
  line L3 (0, 266.7) -> (0, 0)
  line L4 (0, 3.048) -> (-6.35, 3.048)
  line L5 (-95.6809, 124.2466) -> (-95.6809, 124.2212)
  line L6 (-50.8, 266.7) -> (-50.8, 241.7989)
  line L7 (0, 266.7) -> (-50.8, 266.7)
  curve K19 (-71.6837, 232.5587) -> (-50.8, 241.7989)
  curve K20 (-50.8, 237.8015) -> (-50.8, 241.7989)
  curve K21 (-53.6019, 236.5654) -> (-50.8, 237.8015)
  curve K22 (-59.7861, 236.0598) -> (-53.6019, 236.5654)
  curve K23 (-64.4375, 235.2772) -> (-59.7861, 236.0598)
  curve K24 (-69.8917, 233.4707) -> (-64.4375, 235.2772)
  curve K25 (-71.6837, 232.5587) -> (-69.8917, 233.4707)
  curve K26 (-71.6837, 232.5587) -> (-95.6809, 124.2466)
  curve K27 (-95.6814, 136.0132) -> (-95.6809, 124.2466)
  curve K28 (-95.1681, 153.1357) -> (-95.6814, 136.0132)
  curve K29 (-94.696, 167.1533) -> (-95.1681, 153.1357)
  curve K30 (-94.3798, 177.9523) -> (-94.696, 167.1533)
  curve K31 (-93.5014, 190.1145) -> (-94.3798, 177.9523)
  curve K32 (-92.6826, 197.8306) -> (-93.5014, 190.1145)
  curve K33 (-87.4432, 214.7737) -> (-92.6826, 197.8306)
  curve K34 (-83.6663, 221.0115) -> (-87.4432, 214.7737)
  curve K35 (-81.2455, 224.7759) -> (-83.6663, 221.0115)
  curve K36 (-79.8608, 226.3684) -> (-81.2455, 224.7759)
  curve K37 (-77.083, 228.9361) -> (-79.8608, 226.3684)
  curve K38 (-75.5537, 230.2778) -> (-77.083, 228.9361)
  curve K39 (-71.6837, 232.5587) -> (-75.5537, 230.2778)
  curve K40 (-50.8, 244.8458) -> (-50.8, 244.8469)
  curve K41 (-50.8, 244.8465) -> (-50.8, 244.8469)
  curve K42 (-50.8, 244.8462) -> (-50.8, 244.8465)
  curve K43 (-50.8, 244.8458) -> (-50.8, 244.8462)
  arc A1 centre (-13.3279, 188.7329) radius 185.6867 clockwise from (-14.1394, 3.048) to (-52.8501, 7.301)
  point P26 (0, 3.048)
  point P33 (-50.8, 237.8015)
  point P35 (-50.8, 237.8015)
  point P40 (-71.6837, 232.5587)
  point P53 (-50.8, 244.8458)
  coincident L3 P26
  perpendicular L3 L4
  coincident P33 P35
  coincident K19 P40
  coincident L6 P53
sketch "Sketch2" plane through (0, 0, 0) normal (0, 1, 0) x axis (1, 0, 0)
  line L1 (-95.6809, 124.1958) -> (-95.6809, 124.2212)
  line L2 (0, 266.7) -> (-50.8, 266.7)
  curve K1 (-58.9317, 239.3909) -> (-50.8, 244.8469)
  curve K2 (-50.8, 244.602) -> (-50.8, 244.8469)
  curve K3 (-50.904, 243.981) -> (-50.8, 244.602)
  curve K4 (-51.2936, 243.3317) -> (-50.904, 243.981)
  curve K5 (-51.734, 242.8041) -> (-51.2936, 243.3317)
  curve K6 (-53.328, 241.5518) -> (-51.734, 242.8041)
  curve K7 (-54.0892, 241.2477) -> (-53.328, 241.5518)
  curve K8 (-58.9317, 239.3909) -> (-54.0892, 241.2477)
  line L3 (-50.8, 266.7) -> (-50.8, 244.8458)
  curve K9 (-52.8501, 7.301) -> (-95.6809, 124.1958)
  curve K10 (-95.6814, 112.4293) -> (-95.6809, 124.1958)
  curve K11 (-95.1681, 95.3068) -> (-95.6814, 112.4293)
  curve K12 (-94.696, 81.2892) -> (-95.1681, 95.3068)
  curve K13 (-94.3798, 70.4902) -> (-94.696, 81.2892)
  curve K14 (-93.5014, 58.328) -> (-94.3798, 70.4902)
  curve K15 (-92.6826, 50.6119) -> (-93.5014, 58.328)
  curve K16 (-87.4432, 33.6688) -> (-92.6826, 50.6119)
  curve K17 (-83.6663, 27.4309) -> (-87.4432, 33.6688)
  curve K18 (-81.2455, 23.6666) -> (-83.6663, 27.4309)
  curve K19 (-79.8608, 22.0741) -> (-81.2455, 23.6666)
  curve K20 (-76.5846, 19.0457) -> (-79.8608, 22.0741)
  curve K21 (-73.7599, 16.6033) -> (-76.5846, 19.0457)
  curve K22 (-65.532, 11.7145) -> (-73.7599, 16.6033)
  curve K23 (-60.3553, 9.483) -> (-65.532, 11.7145)
  curve K24 (-55.4987, 7.9411) -> (-60.3553, 9.483)
  curve K25 (-54.6982, 7.6526) -> (-55.4987, 7.9411)
  curve K26 (-52.8501, 7.301) -> (-54.6982, 7.6526)
  line L4 (-95.6809, 124.2466) -> (-95.6809, 124.2212)
  line L5 (0, 3.048) -> (-6.35, 3.048)
  line L6 (-6.35, 3.048) -> (-14.1394, 3.048)
  curve K27 (-58.9317, 239.3909) -> (-95.6809, 124.2466)
  curve K28 (-95.6814, 136.0132) -> (-95.6809, 124.2466)
  curve K29 (-95.1681, 153.1357) -> (-95.6814, 136.0132)
  curve K30 (-94.696, 167.1533) -> (-95.1681, 153.1357)
  curve K31 (-94.3798, 177.9523) -> (-94.696, 167.1533)
  curve K32 (-93.5014, 190.1145) -> (-94.3798, 177.9523)
  curve K33 (-92.6826, 197.8306) -> (-93.5014, 190.1145)
  curve K34 (-87.4432, 214.7737) -> (-92.6826, 197.8306)
  curve K35 (-83.6663, 221.0115) -> (-87.4432, 214.7737)
  curve K36 (-81.2455, 224.7759) -> (-83.6663, 221.0115)
  curve K37 (-79.8608, 226.3684) -> (-81.2455, 224.7759)
  curve K38 (-76.5846, 229.3968) -> (-79.8608, 226.3684)
  curve K39 (-73.7599, 231.8391) -> (-76.5846, 229.3968)
  curve K40 (-65.833, 236.5491) -> (-73.7599, 231.8391)
  curve K41 (-61.4585, 238.4785) -> (-65.833, 236.5491)
  curve K42 (-58.9317, 239.3909) -> (-61.4585, 238.4785)
  line L7 (0, 3.048) -> (0, 266.7)
  arc A1 centre (-13.3279, 188.7329) radius 185.6867 clockwise from (-14.1394, 3.048) to (-52.8501, 7.301)
  point P52 (-50.8, 244.8458)
  coincident K1 P52
  perpendicular L5 L7
revolve "Revolve1" sketch "Sketch1" AlongAngle 360 bodies "Balon v3.3"
shell "Shell1" innerThickness 3.81
revolve "Revolve2" sketch "Sketch2" AlongAngle 360 bodies "Balon v3.2"
shell "Shell2" innerThickness 3.81
component_from_bodies "Body->Comp1"
component_from_bodies "Body->Comp2"
position "Position1"
remove_instance "RemoveInstance1" bodies "Balon v3"
remove_instance "RemoveInstance2"
move "Move1"
position "Position2" bodies "Balon v3"
sketch "Sketch3" plane through (0, 0, 0) normal (0, 1, 0) x axis (1, 0, 0)
  line L1 (0, 50.8) -> (0, -304.8)
  line L2 (127, 50.8) -> (127, -304.8)
  line L3 (-127, 50.8) -> (-127, -304.8)
  line L4 (139.7, 25.4) -> (-139.7, 25.4)
  line L5 (139.7, -292.1) -> (-139.7, -292.1)
  line L6 (95.25, 50.8) -> (95.25, -304.8)
  vertical L1
  dimension "d6" = 127
  dimension "d12" = -127
  dimension "d17" distance L4 L5 = 317.5
  dimension "d18" = 95.25
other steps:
base_feature "Base Feature1" bodies "Balon v3.3"
base_feature "Base Feature1" bodies "Balon v3.2"
base_feature "Base Feature1" bodies "Balon"
base_feature "Base Feature1" bodies "Balon v3"
base_feature "Base Feature1" bodies "Balon v2"
create_component "CreateComponent1"
remove_body "RemoveBody1"
create_component "CreateComponent2"
remove_body "RemoveBody2"
create_component "CreateComponent3"
remove_body "RemoveBody3" bodies "Balon v3"
create_component "CreateComponent1"
create_component "CreateComponent2"
remove_body "RemoveBody1" bodies "Balon v3"
create_component "CreateComponent3"
remove_body "RemoveBody2" bodies "Balon v3"
named bodies: "Balon", "Balon v2", "Balon v3", "Balon v3.3", "Balon v3.2"

design "T8 LED 11" references "T9 - Bulb"
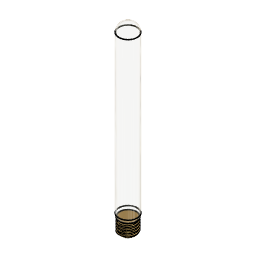
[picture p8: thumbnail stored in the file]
sketch "Sketch1" plane through (0, 0, 0) normal (0, 0, 1) x axis (1, 0, 0)
  circle C1 centre (0, 0) radius 14.986
  point P1 (0, 0)
  point P2 (0, 0)
  coincident P1 P2
  dimension "d1" diameter C1 = 29.972
sketch "Sketch2" plane through (0, 0, 0) normal (0, 1, 0) x axis (1, 0, 0)
  line L1 (0, -273.05) -> (0, 2.54)
  line L2 (15.24, -2.54) -> (15.24, -257.81)
  line L3 (-15.24, -257.81) -> (-15.24, -2.54)
  line L4 (0, 12.7) -> (0, -273.05)
  line L5 (-15.24, 2.54) -> (15.24, 2.54)
  arc A1 centre (0, -2.54) radius 15.24 clockwise from (-15.24, -2.54) to (15.24, -2.54)
  arc A2 centre (0, -257.81) radius 15.24 clockwise from (15.24, -257.81) to (-15.24, -257.81)
  point P2 (0, -273.05)
  point P9 (0, 12.7)
  point P12 (0, 2.54)
  point P1 (0, 0)
  vertical L1
  tangent L2 A1
  tangent A1 L3
  parallel L2 L3
  tangent L3 A2
  tangent L2 A2
  midpoint P2 A2
  midpoint A1 P9
  parallel L1 L4
  horizontal L5
  coincident L5 P12
  dimension "d2" distance P1 P2 = 273.05
revolve "Revolve1" sketch "Sketch2" AlongAngle 360
shell "Shell1" innerThickness 0.9906
external_derived "ExternalDerived1" bodies "E26 Base"
align "Align1"
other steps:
derived_base_feature "Derived Base Feature" bodies "E26 Base"
named bodies: "E26 Base"

design "Chinois"
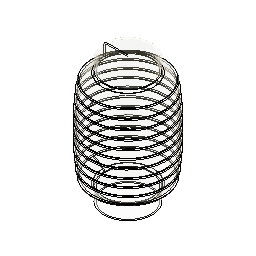
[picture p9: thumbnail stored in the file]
named bodies: "Chinois"

design "2-Pole Plug End"
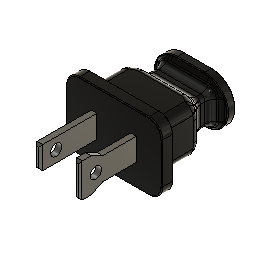
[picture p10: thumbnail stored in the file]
sketch "Sketch1" plane through (0, 0, 0) normal (0, 1, 0) x axis (1, 0, 0)
  line L1 (9.6837, 9.525) -> (-9.6837, 9.525)
  line L2 (13.4938, -5.715) -> (13.4938, 5.715)
  line L3 (-9.6837, -9.525) -> (9.6837, -9.525)
  line L4 (-13.4937, 5.715) -> (-13.4937, -5.715)
  line L5 (13.4938, -9.525) -> (-13.4937, 9.525)
  line L6 (-13.4937, -9.525) -> (13.4938, 9.525)
  arc A1 centre (-9.6837, -5.715) radius 3.81 clockwise from (-9.6837, -9.525) to (-13.4937, -5.715)
  arc A2 centre (9.6837, -5.715) radius 3.81 clockwise from (13.4938, -5.715) to (9.6837, -9.525)
  arc A3 centre (9.6837, 5.715) radius 3.81 clockwise from (9.6837, 9.525) to (13.4938, 5.715)
  arc A4 centre (-9.6837, 5.715) radius 3.81 clockwise from (-13.4937, 5.715) to (-9.6837, 9.525)
  point P6 (0, 0)
  point P1 (0, 0)
  point P5 (-13.4937, -9.525)
  point P4 (13.4938, -9.525)
  point P3 (13.4938, 9.525)
  point P2 (-13.4937, 9.525)
  horizontal L1
  perpendicular L1 L2
  parallel L1 L3
  parallel L2 L4
  coincident L5 P6
  coincident L6 P6
  coincident P1 P6
  coincident P5 L4
  coincident P5 L3
  tangent L4 A1
  tangent L3 A1
  coincident P4 L3
  coincident P4 L2
  tangent L3 A2
  tangent L2 A2
  equal A1 A2
  coincident P3 L2
  coincident P3 L1
  tangent L2 A3
  tangent L1 A3
  equal A1 A3
  coincident P2 L1
  coincident P2 L4
  tangent L1 A4
  tangent L4 A4
  equal A1 A4
  dimension "d1" distance P4 P5 = 26.9875
  dimension "d2" distance P2 P5 = 19.05
  dimension "d3" radius A1 = 3.81
extrude "Extrude1" new body sketch "Sketch1" profile of L1 L2 L3 L4 A1 A2 A3 A4 along normal blind 3.175
sketch "Sketch2" plane through (0, 3.175, 0) normal (0, 1, 0) x axis (-1, 0, 0)
  line L1 (9.6837, -9.525) -> (-9.6837, -9.525)
  line L2 (13.4937, 5.715) -> (13.4937, -5.715)
  line L3 (-9.6837, 9.525) -> (9.6837, 9.525)
  line L4 (-13.4938, -5.715) -> (-13.4938, 5.715)
  line L5 (10.16, -6.35) -> (-10.16, -6.35)
  line L6 (10.16, 6.35) -> (10.16, -6.35)
  line L7 (-10.16, 6.35) -> (10.16, 6.35)
  line L8 (-10.16, -6.35) -> (-10.16, 6.35)
  line L9 (10.16, 6.35) -> (-10.16, -6.35)
  line L10 (-10.16, 6.35) -> (10.16, -6.35)
  arc A1 centre (-9.6837, -5.715) radius 3.81 clockwise from (-9.6837, -9.525) to (-13.4938, -5.715)
  arc A2 centre (9.6837, -5.715) radius 3.81 clockwise from (13.4937, -5.715) to (9.6837, -9.525)
  arc A3 centre (9.6837, 5.715) radius 3.81 clockwise from (9.6837, 9.525) to (13.4937, 5.715)
  arc A4 centre (-9.6837, 5.715) radius 3.81 clockwise from (-13.4938, 5.715) to (-9.6837, 9.525)
  point P18 (0, 0)
  point P1 (0, 0)
  horizontal L5
  perpendicular L5 L6
  parallel L5 L7
  parallel L6 L8
  coincident L9 P18
  coincident L10 P18
  coincident P1 P18
extrude "Extrude2" add sketch "Sketch2" profile of L5 L6 L7 L8 along normal blind 9.525
sketch "Sketch3" plane through (0, 12.7, 0) normal (0, 1, 0) x axis (-1, 0, 0)
  line L1 (-10.16, -6.35) -> (-10.16, 6.35)
  line L2 (10.16, -6.35) -> (-10.16, -6.35)
  line L3 (10.16, 6.35) -> (10.16, -6.35)
  line L4 (-10.16, 6.35) -> (10.16, 6.35)
  line L5 (-7.1437, 3.9688) -> (7.1437, 3.9688)
  line L6 (-7.1437, -3.9688) -> (-7.1437, 3.9688)
  line L7 (7.1437, -3.9688) -> (-7.1437, -3.9688)
  line L8 (7.1437, 3.9688) -> (7.1437, -3.9688)
  line L9 (-7.1437, -3.9688) -> (7.1437, 3.9688)
  line L10 (7.1437, -3.9688) -> (-7.1437, 3.9688)
  point P10 (0, 0)
  point P1 (0, 0)
  point P8 (-7.1437, -3.9688)
  point P9 (7.1437, -3.9688)
  point P7 (-7.1437, 3.9688)
  horizontal L5
  perpendicular L5 L6
  parallel L5 L7
  parallel L6 L8
  coincident L9 P10
  coincident L10 P10
  coincident P1 P10
  dimension "d8" distance P8 P9 = 14.2875
  dimension "d9" distance P7 P8 = 7.9375
extrude "Extrude3" add sketch "Sketch3" profile of L5 L6 L7 L8 along normal blind 11.1125
fillet "Fillet1" radius 2.286 1.27 0.254
chamfer "Chamfer1" distance 3.429
fillet "Fillet2" radius 2.54 1.905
